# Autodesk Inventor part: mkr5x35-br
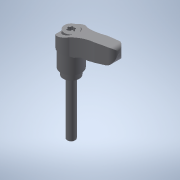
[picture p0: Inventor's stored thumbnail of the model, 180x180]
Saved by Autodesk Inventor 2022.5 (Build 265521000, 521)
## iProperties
Created: 2017-09
Part Number: mkr5x35-br
Material: 一般
Document SubType Name: Modeling
Designer: imaocorp
Density: 1 g/cm^3
Appearance: 既定
Author: imaocorp
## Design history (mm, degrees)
node "mkr5x35-br.x_t1"
node "mkr5x35-br"
node "Base1"
